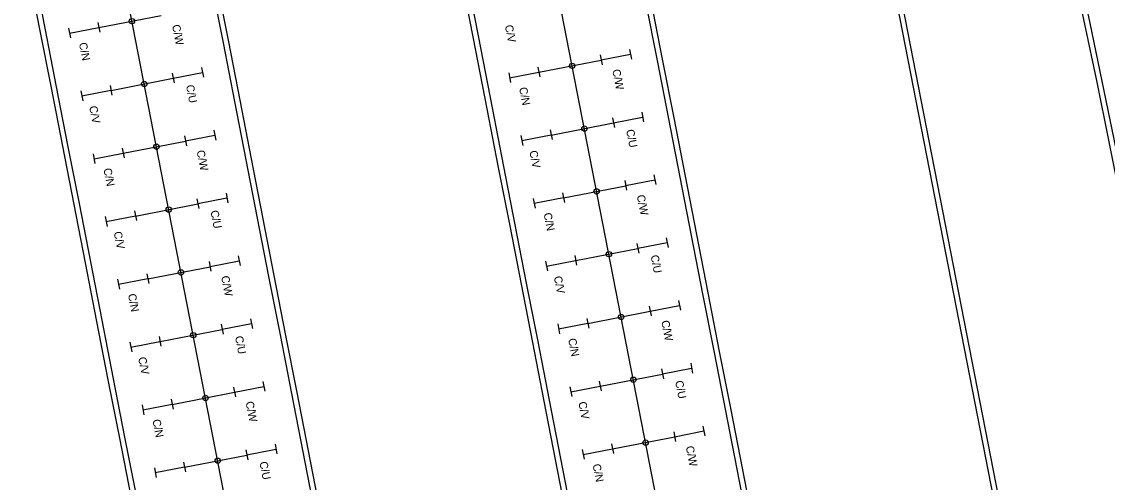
# Model space of a CAD drawing. Extents: x -545258 to -544992, y -1122311 to -1121664.
# Drawn here: x -545222.58 to -545186.13, y -1121748.89 to -1121733.41 of the extents above; entities that cross this region are included whole.
import ezdxf

# ---------------------------------------------------------------- set-up
doc = ezdxf.new("R2010")
doc.units = 0
for name, color, linetype in [('SO18-15-04', 7, 'Continuous'), ('SO18-15-08', 7, 'Continuous'), ('SO18-16-02', 7, 'Continuous'), ('so180605', 7, 'Continuous')]:
    doc.layers.add(name, color=color, linetype=linetype)

msp = doc.modelspace()

# ---------------------------------------------------------------- linework, layer by layer
at = {"layer": 'SO18-15-04'}
for centre in [(-545218.879, -1121733.395), (-545204.099, -1121734.895), (-545218.468, -1121735.506), (-545203.688, -1121737.005), (-545218.057, -1121737.616), (-545203.277, -1121739.116), (-545217.645, -1121739.726), (-545202.865, -1121741.226), (-545217.234, -1121741.837), (-545202.454, -1121743.336), (-545216.823, -1121743.947), (-545202.043, -1121745.446), (-545216.411, -1121746.057), (-545201.631, -1121747.557), (-545216, -1121748.167)]:
    msp.add_circle(centre, 0.09, dxfattribs=at)
at = {"layer": 'SO18-16-02'}
for points in [[(-545165.36, -1121875.544), (-545165.958, -1121872.474), (-545200.812, -1121693.69)], [(-545165.183, -1121875.509), (-545165.782, -1121872.44), (-545200.635, -1121693.656)], [(-545185.121, -1121741.281), (-545185.233, -1121740.707), (-545185.506, -1121739.317), (-545185.897, -1121737.362), (-545186.296, -1121735.409), (-545186.702, -1121733.458), (-545187.116, -1121731.508)], [(-545222.363, -1121731.705), (-545221.981, -1121733.668), (-545221.598, -1121735.631), (-545221.215, -1121737.594), (-545220.833, -1121739.557), (-545220.45, -1121741.52), (-545220.067, -1121743.483), (-545219.685, -1121745.446), (-545219.302, -1121747.409), (-545218.919, -1121749.372), (-545218.537, -1121751.335), (-545218.154, -1121753.299), (-545217.772, -1121755.262), (-545217.389, -1121757.225), (-545217.006, -1121759.188), (-545216.624, -1121761.151), (-545216.241, -1121763.114), (-545215.858, -1121765.077), (-545215.476, -1121767.04), (-545215.093, -1121769.003), (-545214.71, -1121770.966)], [(-545222.187, -1121731.671), (-545221.804, -1121733.634), (-545221.421, -1121735.597), (-545221.039, -1121737.56), (-545220.656, -1121739.523), (-545220.273, -1121741.486), (-545219.891, -1121743.449), (-545219.508, -1121745.412), (-545219.125, -1121747.375), (-545218.743, -1121749.338), (-545218.36, -1121751.301), (-545217.977, -1121753.264), (-545217.595, -1121755.227), (-545217.212, -1121757.19), (-545216.83, -1121759.153), (-545216.447, -1121761.116), (-545216.064, -1121763.079), (-545215.682, -1121765.042), (-545215.299, -1121767.005), (-545214.916, -1121768.969), (-545214.534, -1121770.932)], [(-545185.298, -1121741.315), (-545185.41, -1121740.742), (-545185.683, -1121739.352), (-545186.073, -1121737.398), (-545186.472, -1121735.446), (-545186.878, -1121733.495), (-545187.292, -1121731.546)], [(-545208.539, -1121771.424), (-545208.921, -1121769.461), (-545209.304, -1121767.498), (-545209.687, -1121765.535), (-545210.069, -1121763.572), (-545210.452, -1121761.609), (-545210.835, -1121759.646), (-545211.217, -1121757.683), (-545211.6, -1121755.72), (-545211.983, -1121753.756), (-545212.365, -1121751.793), (-545212.748, -1121749.83), (-545213.13, -1121747.867), (-545213.513, -1121745.904), (-545213.896, -1121743.941), (-545214.278, -1121741.978), (-545214.661, -1121740.015), (-545215.044, -1121738.052), (-545215.426, -1121736.089), (-545215.809, -1121734.126), (-545216.192, -1121732.163)], [(-545208.362, -1121771.39), (-545208.745, -1121769.426), (-545209.127, -1121767.463), (-545209.51, -1121765.5), (-545209.893, -1121763.537), (-545210.275, -1121761.574), (-545210.658, -1121759.611), (-545211.041, -1121757.648), (-545211.423, -1121755.685), (-545211.806, -1121753.722), (-545212.188, -1121751.759), (-545212.571, -1121749.796), (-545212.954, -1121747.833), (-545213.336, -1121745.87), (-545213.719, -1121743.907), (-545214.102, -1121741.944), (-545214.484, -1121739.981), (-545214.867, -1121738.018), (-545215.25, -1121736.055), (-545215.632, -1121734.091), (-545216.015, -1121732.128)], [(-545200.063, -1121771.681), (-545200.446, -1121769.718), (-545200.828, -1121767.755), (-545201.211, -1121765.792), (-545201.593, -1121763.829), (-545201.976, -1121761.866), (-545202.359, -1121759.903), (-545202.741, -1121757.94), (-545203.124, -1121755.977), (-545203.507, -1121754.014), (-545203.889, -1121752.051), (-545204.272, -1121750.088), (-545204.655, -1121748.124), (-545205.037, -1121746.161), (-545205.42, -1121744.198), (-545205.803, -1121742.235), (-545206.185, -1121740.272), (-545206.568, -1121738.309), (-545206.951, -1121736.346), (-545207.333, -1121734.383), (-545207.716, -1121732.42)], [(-545199.886, -1121771.647), (-545200.269, -1121769.684), (-545200.651, -1121767.721), (-545201.034, -1121765.758), (-545201.417, -1121763.794), (-545201.799, -1121761.831), (-545202.182, -1121759.868), (-545202.565, -1121757.905), (-545202.947, -1121755.942), (-545203.33, -1121753.979), (-545203.713, -1121752.016), (-545204.095, -1121750.053), (-545204.478, -1121748.09), (-545204.861, -1121746.127), (-545205.243, -1121744.164), (-545205.626, -1121742.201), (-545206.009, -1121740.238), (-545206.391, -1121738.275), (-545206.774, -1121736.312), (-545207.157, -1121734.349), (-545207.539, -1121732.386)], [(-545201.631, -1121732.749), (-545201.248, -1121734.712), (-545200.865, -1121736.675), (-545200.483, -1121738.638), (-545200.1, -1121740.601), (-545199.717, -1121742.564), (-545199.335, -1121744.527), (-545198.952, -1121746.49), (-545198.569, -1121748.453), (-545198.187, -1121750.416), (-545197.804, -1121752.379), (-545197.421, -1121754.342), (-545197.039, -1121756.305), (-545196.656, -1121758.268), (-545196.273, -1121760.231), (-545195.891, -1121762.195), (-545195.508, -1121764.158), (-545195.126, -1121766.121), (-545194.743, -1121768.084), (-545194.36, -1121770.047), (-545193.978, -1121772.01)], [(-545201.454, -1121732.714), (-545201.071, -1121734.677), (-545200.689, -1121736.64), (-545200.306, -1121738.604), (-545199.923, -1121740.567), (-545199.541, -1121742.53), (-545199.158, -1121744.493), (-545198.775, -1121746.456), (-545198.393, -1121748.419), (-545198.01, -1121750.382), (-545197.627, -1121752.345), (-545197.245, -1121754.308), (-545196.862, -1121756.271), (-545196.479, -1121758.234), (-545196.097, -1121760.197), (-545195.714, -1121762.16), (-545195.331, -1121764.123), (-545194.949, -1121766.086), (-545194.566, -1121768.049), (-545194.183, -1121770.012), (-545193.801, -1121771.975)]]:
    msp.add_lwpolyline(points, dxfattribs=at)
at = {"layer": 'so180605'}
for p, q in [((-545221.008, -1121733.63), (-545220.944, -1121733.959)), ((-545220.977, -1121733.796), (-545219.995, -1121733.605)), ((-545220.026, -1121733.442), (-545219.962, -1121733.767)), ((-545202.174, -1121734.342), (-545202.11, -1121734.668)), ((-545203.156, -1121734.531), (-545203.092, -1121734.859)), ((-545203.125, -1121734.697), (-545202.143, -1121734.506)), ((-545217.524, -1121735.142), (-545217.46, -1121735.47)), ((-545217.493, -1121735.308), (-545216.512, -1121735.117)), ((-545216.542, -1121734.953), (-545216.479, -1121735.279)), ((-545206.228, -1121735.13), (-545206.164, -1121735.458)), ((-545206.197, -1121735.296), (-545205.215, -1121735.105)), ((-545205.246, -1121734.941), (-545205.182, -1121735.267)), ((-545219.615, -1121735.552), (-545219.551, -1121735.878)), ((-545220.597, -1121735.74), (-545220.533, -1121736.069)), ((-545220.566, -1121735.907), (-545219.584, -1121735.715)), ((-545202.744, -1121736.641), (-545202.68, -1121736.97)), ((-545202.713, -1121736.807), (-545201.732, -1121736.616)), ((-545201.762, -1121736.453), (-545201.699, -1121736.778)), ((-545217.113, -1121737.252), (-545217.049, -1121737.58)), ((-545217.082, -1121737.418), (-545216.101, -1121737.227)), ((-545216.131, -1121737.063), (-545216.067, -1121737.389)), ((-545205.817, -1121737.24), (-545205.753, -1121737.568)), ((-545205.786, -1121737.406), (-545204.804, -1121737.215)), ((-545204.834, -1121737.051), (-545204.771, -1121737.377)), ((-545219.203, -1121737.662), (-545219.14, -1121737.988)), ((-545220.185, -1121737.851), (-545220.121, -1121738.179)), ((-545220.154, -1121738.017), (-545219.173, -1121737.826)), ((-545202.333, -1121738.752), (-545202.269, -1121739.08)), ((-545202.302, -1121738.918), (-545201.321, -1121738.726)), ((-545201.351, -1121738.563), (-545201.287, -1121738.889)), ((-545215.72, -1121739.174), (-545215.656, -1121739.499)), ((-545204.423, -1121739.162), (-545204.36, -1121739.487)), ((-545216.702, -1121739.362), (-545216.638, -1121739.691)), ((-545216.671, -1121739.528), (-545215.689, -1121739.337)), ((-545205.405, -1121739.35), (-545205.341, -1121739.679)), ((-545205.374, -1121739.516), (-545204.393, -1121739.325)), ((-545218.792, -1121739.772), (-545218.728, -1121740.098)), ((-545219.774, -1121739.961), (-545219.71, -1121740.29)), ((-545219.743, -1121740.127), (-545218.761, -1121739.936)), ((-545201.922, -1121740.862), (-545201.858, -1121741.19)), ((-545201.891, -1121741.028), (-545200.909, -1121740.837)), ((-545200.94, -1121740.673), (-545200.876, -1121740.999)), ((-545215.308, -1121741.284), (-545215.245, -1121741.61)), ((-545204.012, -1121741.272), (-545203.948, -1121741.598)), ((-545216.29, -1121741.473), (-545216.226, -1121741.801)), ((-545216.259, -1121741.639), (-545215.278, -1121741.447)), ((-545204.994, -1121741.461), (-545204.93, -1121741.789)), ((-545204.963, -1121741.627), (-545203.981, -1121741.435)), ((-545219.363, -1121742.071), (-545219.298, -1121742.4)), ((-545219.332, -1121742.237), (-545218.35, -1121742.046)), ((-545218.38, -1121741.883), (-545218.317, -1121742.208)), ((-545200.528, -1121742.784), (-545200.465, -1121743.109)), ((-545201.51, -1121742.972), (-545201.446, -1121743.301)), ((-545201.479, -1121743.138), (-545200.498, -1121742.947)), ((-545215.848, -1121743.749), (-545214.867, -1121743.558)), ((-545214.897, -1121743.394), (-545214.833, -1121743.72)), ((-545204.582, -1121743.571), (-545204.518, -1121743.899)), ((-545204.552, -1121743.737), (-545203.57, -1121743.546)), ((-545203.6, -1121743.382), (-545203.537, -1121743.708)), ((-545215.879, -1121743.583), (-545215.815, -1121743.911)), ((-545218.951, -1121744.182), (-545218.887, -1121744.51)), ((-545218.92, -1121744.348), (-545217.939, -1121744.156)), ((-545217.969, -1121743.993), (-545217.906, -1121744.319)), ((-545200.117, -1121744.894), (-545200.053, -1121745.22)), ((-545201.099, -1121745.082), (-545201.035, -1121745.411)), ((-545201.068, -1121745.249), (-545200.086, -1121745.057)), ((-545215.468, -1121745.693), (-545215.404, -1121746.022)), ((-545215.437, -1121745.859), (-545214.455, -1121745.668)), ((-545214.486, -1121745.505), (-545214.422, -1121745.83)), ((-545204.171, -1121745.681), (-545204.107, -1121746.01)), ((-545204.14, -1121745.847), (-545203.159, -1121745.656)), ((-545203.189, -1121745.493), (-545203.126, -1121745.818)), ((-545217.558, -1121746.103), (-545217.494, -1121746.429)), ((-545218.54, -1121746.292), (-545218.476, -1121746.62)), ((-545218.509, -1121746.458), (-545217.527, -1121746.267)), ((-545200.688, -1121747.193), (-545200.624, -1121747.521)), ((-545200.657, -1121747.359), (-545199.675, -1121747.168)), ((-545199.706, -1121747.004), (-545199.642, -1121747.33)), ((-545215.056, -1121747.803), (-545214.992, -1121748.132)), ((-545215.025, -1121747.97), (-545214.044, -1121747.778)), ((-545214.074, -1121747.615), (-545214.011, -1121747.941)), ((-545203.76, -1121747.791), (-545203.696, -1121748.12)), ((-545203.729, -1121747.958), (-545202.747, -1121747.766)), ((-545202.778, -1121747.603), (-545202.714, -1121747.929)), ((-545217.146, -1121748.214), (-545217.083, -1121748.539)), ((-545218.128, -1121748.402), (-545218.064, -1121748.731)), ((-545218.098, -1121748.568), (-545217.116, -1121748.377))]:
    msp.add_line(p, q, dxfattribs=at)
for points in [[(-545198.553, -1121763.364), (-545198.555, -1121763.356), (-545208.624, -1121711.682)], [(-545212.51, -1121766.085), (-545212.512, -1121766.077), (-545222.582, -1121714.403)], [(-545219.993, -1121733.612), (-545217.902, -1121733.205)], [(-545205.213, -1121735.111), (-545203.122, -1121734.704)], [(-545219.581, -1121735.722), (-545217.491, -1121735.315)], [(-545204.801, -1121737.222), (-545202.711, -1121736.815)], [(-545219.17, -1121737.832), (-545217.079, -1121737.425)], [(-545204.39, -1121739.332), (-545202.299, -1121738.925)], [(-545218.759, -1121739.943), (-545216.668, -1121739.536)], [(-545203.979, -1121741.442), (-545201.888, -1121741.035)], [(-545218.347, -1121742.053), (-545216.257, -1121741.646)], [(-545203.567, -1121743.553), (-545201.476, -1121743.146)], [(-545217.936, -1121744.163), (-545215.845, -1121743.756)], [(-545203.156, -1121745.663), (-545201.065, -1121745.256)], [(-545217.525, -1121746.274), (-545215.434, -1121745.867)], [(-545202.745, -1121747.773), (-545200.654, -1121747.366)], [(-545217.113, -1121748.384), (-545215.022, -1121747.977)]]:
    msp.add_lwpolyline(points, dxfattribs=at)

# ---------------------------------------------------------------- texts
at = {"layer": 'SO18-15-08'}
for s, p in [('C/W', (-545217.534, -1121733.535)), ('C/V', (-545206.36, -1121733.545)), ('C/N', (-545220.662, -1121734.138)), ('C/W', (-545202.754, -1121735.035)), ('C/U', (-545217.068, -1121735.558)), ('C/N', (-545205.882, -1121735.638)), ('C/V', (-545220.318, -1121736.266)), ('C/U', (-545202.288, -1121737.057)), ('C/W', (-545216.711, -1121737.756)), ('C/V', (-545205.538, -1121737.766)), ('C/N', (-545219.839, -1121738.359)), ('C/W', (-545201.931, -1121739.255)), ('C/U', (-545216.246, -1121739.778)), ('C/N', (-545205.059, -1121739.858)), ('C/V', (-545219.495, -1121740.487)), ('C/U', (-545201.466, -1121741.278)), ('C/W', (-545215.888, -1121741.976)), ('C/V', (-545204.715, -1121741.986)), ('C/N', (-545219.016, -1121742.579)), ('C/W', (-545201.108, -1121743.476)), ('C/U', (-545215.423, -1121743.999)), ('C/N', (-545204.236, -1121744.079)), ('C/V', (-545218.672, -1121744.707)), ('C/U', (-545200.643, -1121745.498)), ('C/W', (-545215.066, -1121746.197)), ('C/V', (-545203.892, -1121746.207)), ('C/N', (-545218.194, -1121746.8)), ('C/W', (-545200.286, -1121747.696)), ('C/U', (-545214.6, -1121748.219)), ('C/N', (-545203.414, -1121748.299))]:
    msp.add_text(s, height=0.2688, rotation=281.121, dxfattribs=at).set_placement(p)

doc.saveas('drawing.dxf')
